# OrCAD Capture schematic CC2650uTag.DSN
size A4; title: CC2650uTag; rev: 2.0.0
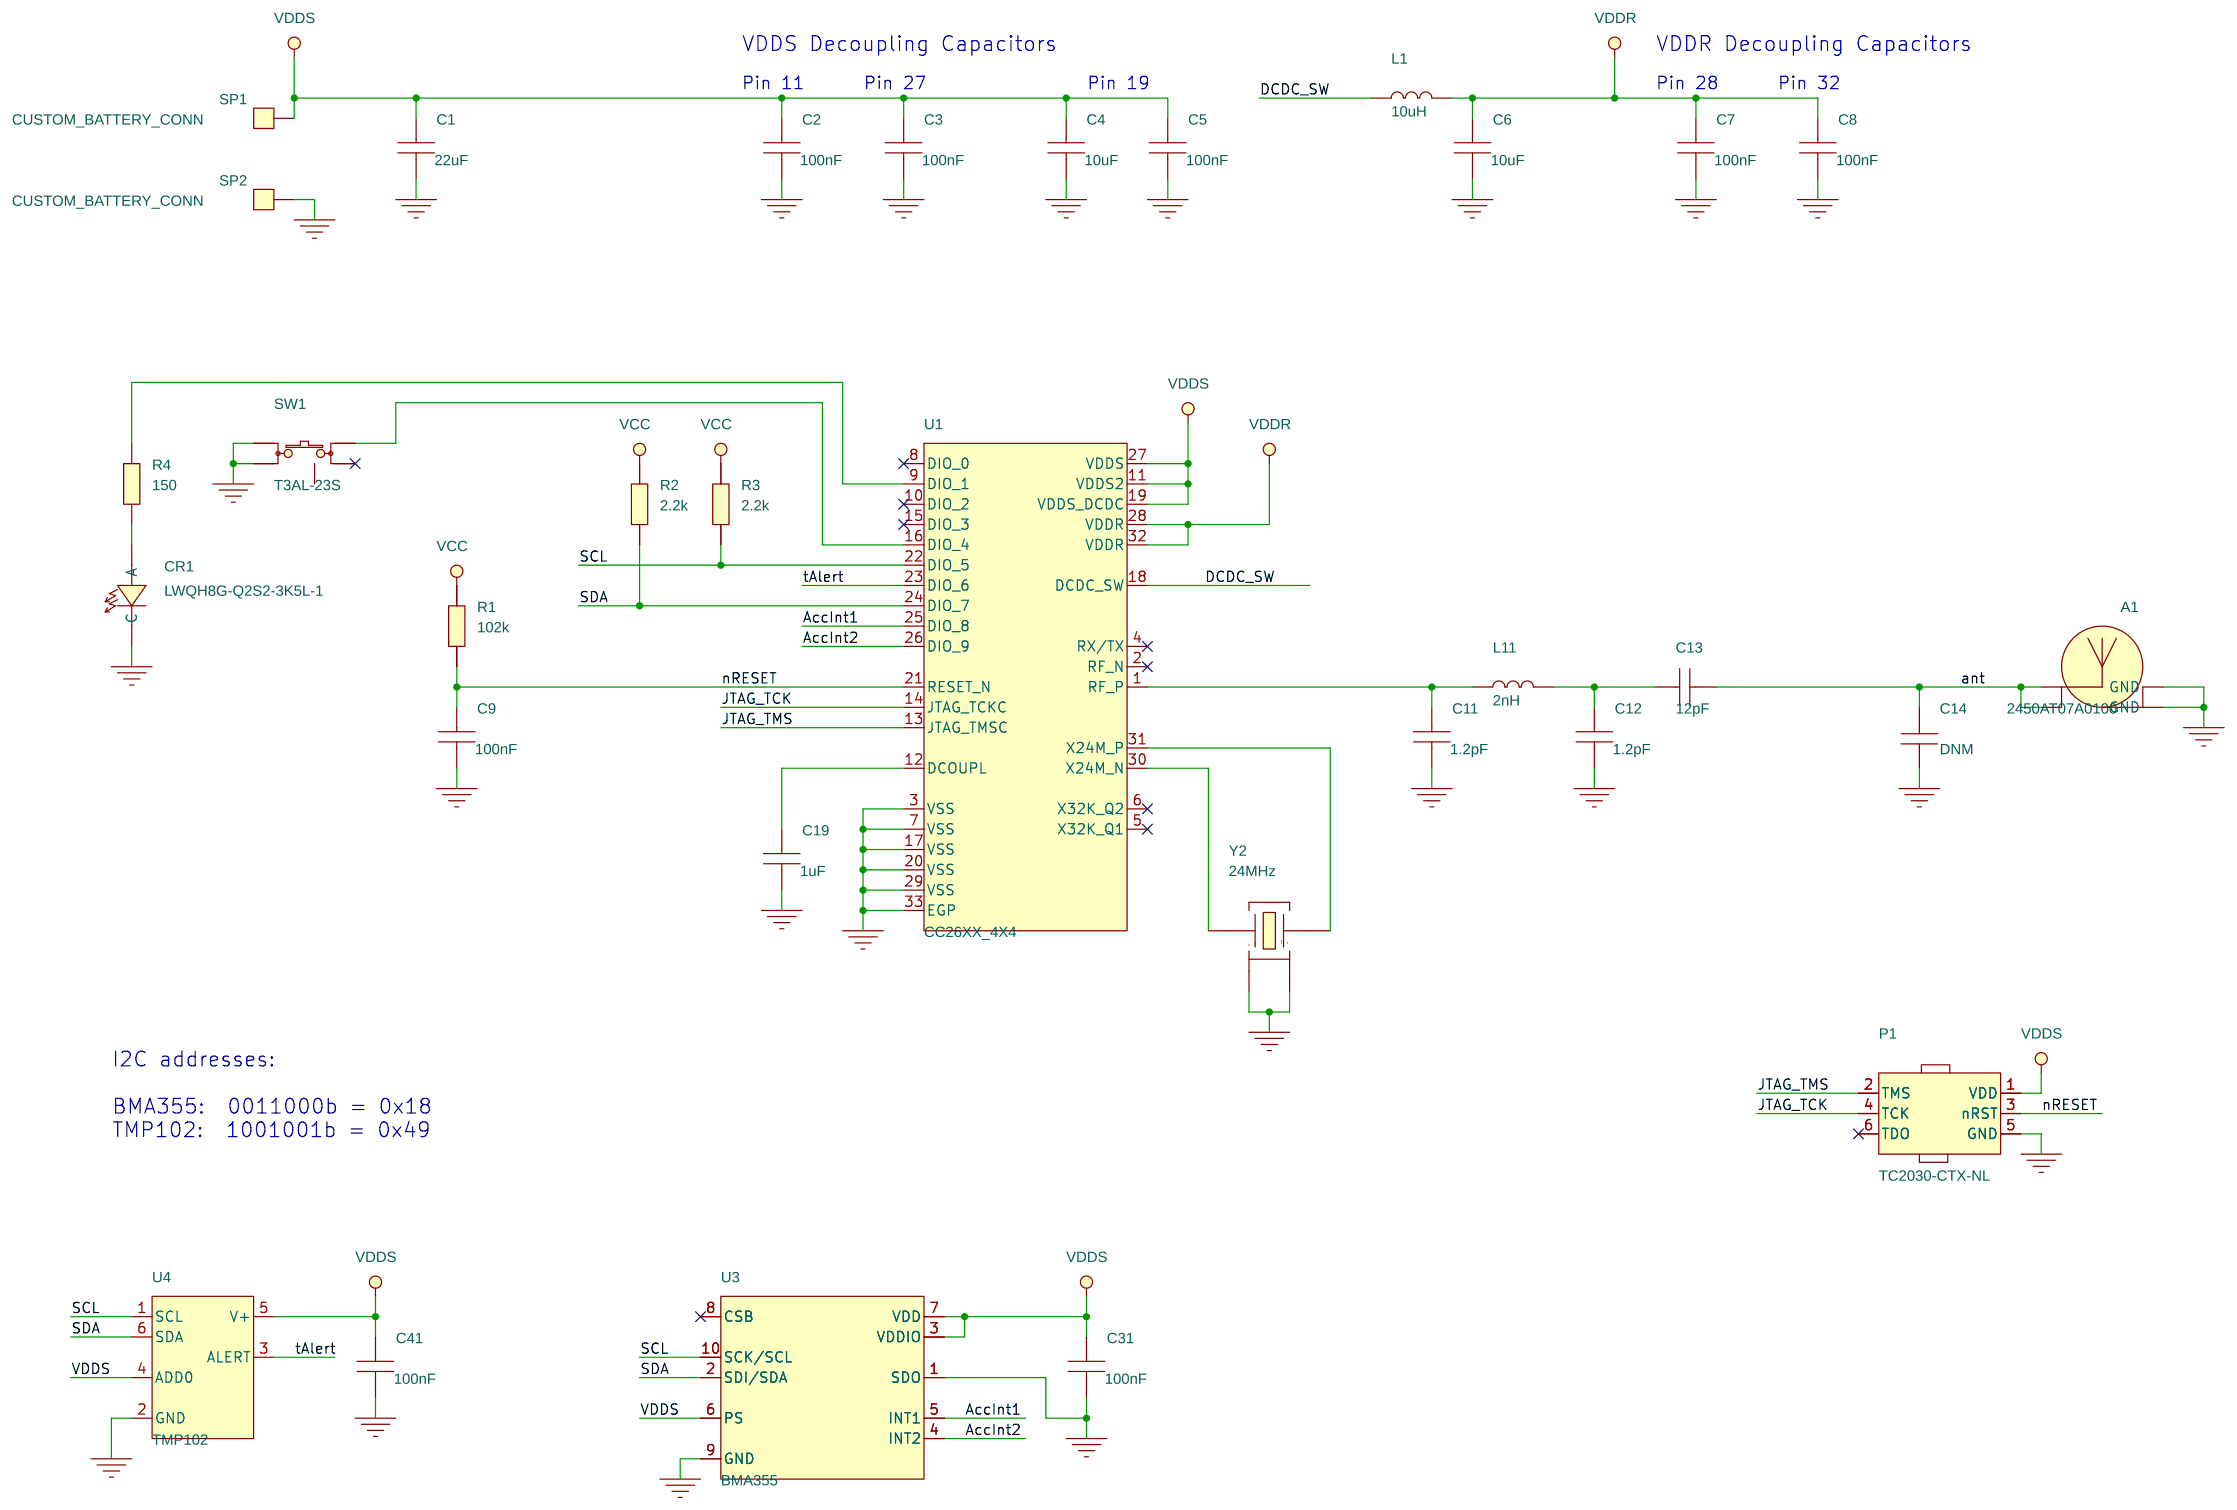
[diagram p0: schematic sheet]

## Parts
A1  2450AT07A0100  [ANTENNA_2450AT07A0100N]
C1  22uF  [CAPC1608X90L]
C2  100nF  [CAPC0603X35L]
C3  100nF  [CAPC0603X35L]
C4  10uF  [CAPC1005X60L]
C5  100nF  [CAPC0603X35L]
C6  10uF  [CAPC1005X60L]
C7  100nF  [CAPC0603X35L]
C8  100nF  [CAPC0603X35L]
C9  100nF  [CAPC0603X35L]
C11  1.2pF  [CAPC0603X35L]
C12  1.2pF  [CAPC0603X35L]
C13  12pF  [CAPC0603X35L]
C14  DNM  [CAPC0603X35L]
C19  1uF  [CAPC1005X60L]
C31  100nF  [CAPC0603X35L]
C41  100nF  [CAPC0603X35L]
CR1  LWQH8G-Q2S2-3K5L-1  [LED_LWQH8GQ2S23K5L1L]
L1  10uH  [INDC1608X100L]
L11  2nH  [INDC1005X60L]
P1  TC2030-CTX-NL  [TAGCONNECT_TC2030-CTX-NLL]
R1  102k  [RESC0603X35L]
R2  2.2k  [RESC0603X35L]
R3  2.2k  [RESC0603X35L]
R4  150  [RESC0603X35L]
SP1  CUSTOM_BATTERY_CONN  [PAD_S2800OBL5000_800M3000]
SP2  CUSTOM_BATTERY_CONN  [PAD_S2800OBL5000_800M3000]
SW1  T3AL-23S  [SW_T3AL23SQTL]
U1  CC26XX_4X4  [QFNFC40P400X400X100-33L]
U3  BMA355  [BGAFC10C40P125X152X80]
U4  TMP102  [SOTFL50P160X60-6L]
Y2  24MHz  [XTAL_FA128L]

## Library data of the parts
A1 = ANTENNA_CERAMIC_4: MECHANIC, ANTENNA, HIGH FREQUENCY CERAMIC, 50, 2.4GHz TO 2.5GHz, SMD; ALT_SYMBOLS: ANTENNA_2450AT07A0100L,ANTENNA_2450AT07A0100M; AutoDoc File: http://notefied-dynamic-precision.com/DB/Apps/Desktop/Item/Object.aspx?id=90750; Datasheet URL 2: http://www.johansontechnology.com/images/stories/ip/rf-antennas/Antenna_2450AT07A0100_v5.pdf; FPLIST: ANTENNA_2450AT07A0100N,ANTENNA_2450AT07A0100L,ANTENNA_2450AT07A0100M; Frequency: 2.4GHz TO 2.5GHz; Impedance: 50; MPN Status: ACTIVE; Manufacturer: JOHANSON DIELECTRICS; Max Oper Temp: +85DEGC; Min Oper Temp: -40DEGC; Mounting Type: SMD; NOTE Status: PREFERRED; Part Number: 13-00495; Part Type: MECHANIC\ANTENNA; Revision: R001; RoHS Status: ROHS_COMPLIANT; Rtd Power: 2W
C1 = CAPACITOR: CAPACITOR, CERAMIC X5R, 22uF, 4V, -20%/+20%, -55DEGC/+85DEGC, 0603, SMD; ALT_SYMBOLS: CAPC1608X90L,CAPC1608X90M; AutoDoc File: http://notefied-dynamic-precision.com/DB/Apps/Desktop/Item/Object.aspx?id=86641; Budget Currency: EUR; Budget Price: 0.122; Datasheet URL 1: http://search.murata.co.jp/Ceramy/image/img/w_hinm/L0005E.pdf; Datasheet URL 2: http://psearch.murata.com/capacitor/product/GRM188R60G226MEA0%23.pdf; Definied Quality: INDUSTRIAL; Dielectric Type: X5R; Esd Level: N/A; FPLIST: CAPC1608X90N,CAPC1608X90L,CAPC1608X90M; Last Time Buy: N/A; Lead Time: 20; MPN: GRM188R60G226MEA0D; MPN Status: ACTIVE; MSL: 1; MTBF: N/A; MTBF Standard: N/A; Manufacturer: MURATA; Max Oper Temp: +85DEGC; Max Tol: +20%; Min Oper Temp: -55DEGC; Min Tol: -20%; Mounting Type: SMD; NOTE Status: PREFERRED; Old Footprint: CAPC1608X90N; PCB Package: 0603; Packing Size: 4000; Packing Type: TAPE_&_REEL; Part Number: 02-04481; Part Type: CAPACITOR\CERAMIC\0603; Revision: R001; RoHS Status: ROHS_COMPLIANT; Rtd Voltage: 4V; WEIGHT: 0.0091g
C2 C3 C5 C7-C9 C31 C41 = CAPACITOR: CAPACITOR, CERAMIC X5R, 100nF, 6.3V, -10%/+10%, -55DEGC/+85DEGC, 0201, SMD; ALT_SYMBOLS: CAPC0603X35L,CAPC0603X35M; AutoDoc File: http://notefied-dynamic-precision.com/DB/Apps/Desktop/Item/Object.aspx?id=82835; Budget Currency: EUR; Budget Price: 0.073; Datasheet URL 1: N/A; Datasheet URL 2: http://www.avx.com/docs/Catalogs/cx5r.pdf; Definied Quality: INDUSTRIAL; Dielectric Type: X5R; FPLIST: CAPC0603X35N,CAPC0603X35L,CAPC0603X35M; Lead Time: 16; MPN: 02016D104KAT2A; MPN Status: ACTIVE; MSL: 1; MTBF: N/A; MTBF Standard: N/A; Manufacturer: AVX; Max Oper Temp: +85DEGC; Max Tol: +10%; Min Oper Temp: -55DEGC; Min Tol: -10%; Mounting Type: SMD; NOTE Status: PREFERRED; Old Footprint: CAPC0603X35N; PCB Package: 0201; Packing Size: 15000; Packing Type: TAPE_&_REEL; Part Number: 02-01686; Part Type: CAPACITOR\CERAMIC\0201; Revision: R002; RoHS Status: ROHS_COMPLIANT; Rtd Voltage: 6.3V; WEIGHT: N/A
C4 C6 = CAPACITOR: CAPACITOR, CERAMIC X5R, 10uF, 6.3V, -20%/+20%, -55DEGC/+85DEGC, 0402, SMD; ALT_SYMBOLS: CAPC1005X60L,CAPC1005X60M; AutoDoc File: http://notefied-dynamic-precision.com/DB/Apps/Desktop/Item/Object.aspx?id=90722; Budget Currency: EUR; Budget Price: 0.13; Datasheet URL 1: N/A; Datasheet URL 2: http://product.tdk.com/capacitor/mlcc/en/documents/C1005X5R0J106M050BC.pdf; Definied Quality: INDUSTRIAL; Dielectric Type: X5R; Esd Level: N/A; FPLIST: CAPC1005X60N,CAPC1005X60L,CAPC1005X60M; Last Time Buy: N/A; Lead Time: 18; MPN: C1005X5R0J106M050BC; MPN Status: ACTIVE; MSL: N/A; MTBF: N/A; MTBF Standard: N/A; Manufacturer: TDK; Max Oper Temp: +85DEGC; Max Tol: +20%; Min Oper Temp: -55DEGC; Min Tol: -20%; Mounting Type: SMD; NOTE Status: PREFERRED; Old Footprint: CAPC1005X60N; PCB Package: 0402; Packing Size: 10000; Packing Type: TAPE_&_REEL; Part Number: 02-05030; Part Type: CAPACITOR\CERAMIC\0402; Revision: R001; RoHS Status: ROHS_COMPLIANT; Rtd Voltage: 6.3V; WEIGHT: N/A
C11 C12 = CAPACITOR: CAPACITOR, CERAMIC C0G/NP0, 1.2pF, 25V, -0.25pF/+0.25pF, -55DEGC/+125DEGC, 0201, SMD; ALT_SYMBOLS: CAPC0603X35L,CAPC0603X35M; AutoDoc File: http://notefied-dynamic-precision.com/DB/Apps/Desktop/Item/Object.aspx?id=85776; Budget Currency: EUR; Budget Price: 0.062; Datasheet URL 1: N/A; Datasheet URL 2: http://www.avx.com/docs/Catalogs/ccog.pdf; Definied Quality: INDUSTRIAL; Dielectric Type: C0G/NP0; FPLIST: CAPC0603X35N,CAPC0603X35L,CAPC0603X35M; Lead Time: 12; LifeCycle Status: ACTIVE; MPN: 02013A1R2CAT2A; MPN Status: ACTIVE; MSL: 1; MTBF: N/A; MTBF Standard: N/A; Manufacturer: AVX; Max Oper Temp: +125DEGC; Max Tol: +0.25pF; Min Oper Temp: -55DEGC; Min Tol: -0.25pF; Mounting Type: SMD; NOTE Status: PREFERRED; Old Footprint: CAPC0603X35N; PCB Package: 0201; Packing Size: 15000; Packing Type: TAPE_&_REEL; Part Number: 02-04266; Part Type: CAPACITOR\CERAMIC\0201; Revision: R001; RoHS Status: ROHS_COMPLIANT; Rtd Voltage: 25V; WEIGHT: 0.000228g
C13 = CAPACITOR: CAPACITOR, CERAMIC C0G/NP0, 12pF, 25V, -5%/+5%, -55DEGC/+125DEGC, 0201, SMD; ALT_SYMBOLS: CAPC0603X35L,CAPC0603X35M; AutoDoc File: http://notefied-dynamic-precision.com/DB/Apps/Desktop/Item/Object.aspx?id=85787; Budget Currency: EUR; Budget Price: 0.043; Datasheet URL 1: N/A; Datasheet URL 2: http://www.avx.com/docs/Catalogs/ccog.pdf; Definied Quality: INDUSTRIAL; Dielectric Type: C0G/NP0; FPLIST: CAPC0603X35N,CAPC0603X35L,CAPC0603X35M; Lead Time: 18; LifeCycle Status: ACTIVE; MPN: 02013A120JAT2A; MPN Status: ACTIVE; MSL: 1; MTBF: N/A; MTBF Standard: N/A; Manufacturer: AVX; Max Oper Temp: +125DEGC; Max Tol: +5%; Min Oper Temp: -55DEGC; Min Tol: -5%; Mounting Type: SMD; NOTE Status: PREFERRED; Old Footprint: CAPC0603X35N; PCB Package: 0201; Packing Size: 15000; Packing Type: TAPE_&_REEL; Part Number: 02-04277; Part Type: CAPACITOR\CERAMIC\0201; Revision: R001; RoHS Status: ROHS_COMPLIANT; Rtd Voltage: 25V; WEIGHT: N/A
C14 = CAPACITOR: CAPACITOR, DO NOT MOUNT, 0201, SMD; ALT_SYMBOLS: CAPC0603X35L,CAPC0603X35N; AutoDoc File: https://notefied-dynamic-precision.com/NotefiedWebServices/AutoDocs.aspx?itemid=50471; FPLIST: CAPC0603X35N,CAPC0603X35L,CAPC0603X35N; Old Footprint: CAPC0603X35N,0201; Part Number: 02-01320; Part Type: CAPACITOR\CERAMIC\0201; Revision: R001
C19 = CAPACITOR: CAPACITOR, CERAMIC X5R, 1uF, 10V, -10%/+10%, -55DEGC/+85DEGC, 0402, SMD; ALT_SYMBOLS: CAPC1005X60L,CAPC1005X60M; AutoDoc File: http://notefied-dynamic-precision.com/DB/Apps/Desktop/Item/Object.aspx?id=74236; Budget Currency: EUR; Budget Price: 0.015; Datasheet URL 1: http://search.murata.co.jp/Ceramy/image/img/w_hinm/L0005E.pdf; Datasheet URL 2: http://psearch.murata.com/capacitor/product/GRM155R61A105KE15%23.pdf; Definied Quality: INDUSTRIAL; Dielectric Type: X5R; Esd Level: N/A; FPLIST: CAPC1005X60N,CAPC1005X60L,CAPC1005X60M; Last Time Buy: N/A; Lead Time: 14; MPN: GRM155R61A105KE15D; MPN Status: ACTIVE; MSL: 1; MTBF: N/A; MTBF Standard: N/A; Manufacturer: MURATA; Max Oper Temp: +85DEGC; Max Tol: +10%; Min Oper Temp: -55DEGC; Min Tol: -10%; Mounting Type: SMD; NOTE Status: PREFERRED; Old Footprint: CAPC1005X60N,0402; PCB Package: 0402; Packing Size: 10000; Packing Type: TAPE_&_REEL; Part Number: 02-02381; Part Type: CAPACITOR\CERAMIC\0402; Revision: R002; RoHS Status: ROHS_COMPLIANT; Rtd Voltage: 10V; WEIGHT: 0.0016g
CR1 = LED: OPTO, LED, InGaN, WHITE, 2.6V TO 3.1V, 0.015A, 0402, SMD; ALT_SYMBOLS: LED_LWQH8GQ2S23K5L1L,LED_LWQH8GQ2S23K5L1M; AutoDoc File: http://notefied-dynamic-precision.com/DB/Apps/Desktop/Item/Object.aspx?id=95594; Datasheet URL 2: http://catalog.osram-os.com/catalogue/catalogue.do;jsessionid=5C056371528898F0F981A18D4C0143E0?act=downloadFile&favOid=0200000200033af5000300b6; FPLIST: LED_LWQH8GQ2S23K5L1N,LED_LWQH8GQ2S23K5L1L,LED_LWQH8GQ2S23K5L1M; MPN: LW QH8G-Q2S2-3K5L-1; MPN Status: ACTIVE; Manufacturer: OSRAM; Max Oper Temp: +85DEGC; Min Oper Temp: -40DEGC; Mounting Type: SMD; NOTE Status: PREFERRED; Old Footprint: LED_LWQH8GQ2S23K5L1N; PCB Package: 0402; Packing Size: 4000; Packing Type: TAPE_&_REEL; Part Number: 15-01260; Part Type: OPTO\LED\0402; Revision: R001; RoHS Status: ROHS_COMPLIANT; Rtd Current: 0.015A; Rtd Voltage: 2.6V TO 3.1V
L1 = INDUCTOR: INDUCTOR, CHIP, 10uH, -20%/+20%, 0.25A, -55DEGC/+125DEGC, 0603, SMD; ALT_SYMBOLS: INDC1608X100L,INDC1608X100M; AutoDoc File: http://notefied-dynamic-precision.com/DB/Apps/Desktop/Item/Object.aspx?id=84900; Budget Currency: EUR; Budget Price: 0.038; Datasheet URL 1: N/A; Datasheet URL 2: http://www.tdk.co.jp/tefe02/e533_mlz.pdf; Definied Quality: INDUSTRIAL; FPLIST: INDC1608X100N,INDC1608X100L,INDC1608X100M; Lead Time: 4; MPN: MLZ1608M100WT000; MPN Status: ACTIVE; MSL: N/A; MTBF: N/A; MTBF Standard: N/A; Manufacturer: TDK; Max Oper Temp: +125DEGC; Max Tol: +20%; Min Oper Temp: -55DEGC; Min Tol: -20%; Mounting Type: SMD; NOTE Status: PREFERRED; Old Footprint: INDC1608X100N; PCB Package: 0603; Packing Size: 4000; Packing Type: TAPE_&_REEL; Part Number: 03-06510; Part Type: INDUCTOR\CHIP\0603; Revision: R001; RoHS Status: ROHS_COMPLIANT; Rtd Current: 0.25A; WEIGHT: 0.004g
L11 = INDUCTOR: INDUCTOR, CHIP, 2nH, -0.3nH/ +0.3nH, 0.3A, -55DEGC/+125DEGC, 0402, SMD; ALT_SYMBOLS: INDC1005X60L,INDC1005X60M; AutoDoc File: http://notefied-dynamic-precision.com/DB/Apps/Desktop/Item/Object.aspx?id=85431; Budget Currency: EUR; Budget Price: 0.021; Datasheet URL 1: http://search.murata.co.jp/Ceramy/image/img/PDF/ENG/L0075S0083LQG15HS.pdf; Datasheet URL 2: http://search.murata.co.jp/Ceramy/image/img/PDF/ENG/L0075S0083LQG15HS.pdf; FPLIST: INDC1005X60N,INDC1005X60L,INDC1005X60M; Frequency: 6GHz; Lead Time: 9; MPN: LQG15HS2N0S02D; MPN Status: ACTIVE; Manufacturer: MURATA; Max Oper Temp: +125DEGC; Max Tol: +0.3nH; Min Oper Temp: -55DEGC; Min Tol: -0.3nH; Mounting Type: SMD; NOTE Status: PREFERRED; Old Footprint: INDC1005X60N; PCB Package: 0402; Packing Size: 10000; Packing Type: TAPE_&_REEL; Part Number: 03-06525; Part Type: INDUCTOR\CHIP\0402; Revision: R001; RoHS Status: ROHS_COMPLIANT; Rtd Current: 0.3A; WEIGHT: 0.001g
P1 = CONN_IDC_TC2030-CTX-NL_0: NON COMPONENT, CONNECTOR CABLE, PLUG OF NAILS, 6 PINS, 2 ROWS, SMD; ALT_SYMBOLS: TAGCONNECT_TC2030-CTX-NLL,TAGCONNECT_TC2030-CTX-NLM; AutoDoc File: http://notefied-dynamic-precision.com/DB/Apps/Desktop/Item/Object.aspx?id=96375; FPLIST: TAGCONNECT_TC2030-CTX-NLN,TAGCONNECT_TC2030-CTX-NLL,TAGCONNECT_TC2030-CTX-NLM; Old Footprint: TAGCONNECT_TC2030-CTX-NLN; Part Number: 19-00447; Part Type: NON_COMPONENT\CONNECTOR; Revision: R001
R1 = RESISTOR: RESISTOR, THICK FILM, 102K, -1%/+1%, 0.05W, 30V, -55DEGC/+125DEGC, 0201, SMD; ALT_SYMBOLS: RESC0603X35L,RESC0603X35M; AutoDoc File: http://notefied-dynamic-precision.com/DB/Apps/Desktop/Item/Object.aspx?id=58760; Budget Currency: EUR; Budget Price: 0.045; Datasheet URL 1: http://www.vishay.com/docs/20035/dcrcwe3.pdf; Datasheet URL 2: http://www.vishay.com/docs/20052/crcw0201e3.pdf; Definied Quality: COMMERCIAL; FPLIST: RESC0603X35N,RESC0603X35L,RESC0603X35M; Lead Time: 8; LifeCycle Status: ACTIVE; MPN: CRCW0201102KFKED; MPN Status: ACTIVE; MSL: 1; MTBF: 1.00*10^10; MTBF Standard: CL=90%; Manufacturer: VISHAY; Max Oper Temp: +125DEGC; Max TC: +100PPM/DEGC; Max Tol: +1%; Min Oper Temp: -55DEGC; Min TC: -100PPM/DEGC; Min Tol: -1%; Mounting Type: SMD; NOTE Status: PREFERRED; Old Footprint: RESC0603X35N,0201; PCB Package: 0201; Packing Size: 10000; Packing Type: TAPE_&_REEL; Part Number: 01-03953; Part Type: RESISTOR\0201\PRECISION; Resistor Type: THICK FILM; Revision: R001; RoHS Status: ROHS_COMPLIANT; Rtd Power: 0.05W; Rtd Voltage: 30V; WEIGHT: 0.00017g
R2 R3 = RESISTOR: RESISTOR, THICK FILM, 2K2, -1%/+1%, 0.05W, 30V, -55DEGC/+125DEGC, 0201, SMD; ALT_SYMBOLS: RESC0603X35L,RESC0603X35M; AutoDoc File: http://notefied-dynamic-precision.com/DB/Apps/Desktop/Item/Object.aspx?id=58879; Budget Currency: EUR; Budget Price: 0.045; Datasheet URL 1: http://www.vishay.com/docs/20035/dcrcwe3.pdf; Datasheet URL 2: http://www.vishay.com/docs/20052/crcw0201e3.pdf; Definied Quality: COMMERCIAL; FPLIST: RESC0603X35N,RESC0603X35L,RESC0603X35M; Lead Time: 9; LifeCycle Status: ACTIVE; MPN: CRCW02012K20FKED; MPN Status: ACTIVE; MSL: 1; MTBF: 1.00*10^10; MTBF Standard: CL=90%; Manufacturer: VISHAY; Max Oper Temp: +155DEGC; Max TC: +100PPM/DEGC; Max Tol: +1%; Min Oper Temp: -55DEGC; Min TC: -100PPM/DEGC; Min Tol: -1%; Mounting Type: SMD; NOTE Status: PREFERRED; Old Footprint: RESC0603X35N,0201; PCB Package: 0201; Packing Size: 10000; Packing Type: TAPE_&_REEL; Part Number: 01-04072; Part Type: RESISTOR\0201\PRECISION; Resistor Type: THICK FILM; Revision: R001; RoHS Status: ROHS_COMPLIANT; Rtd Power: 0.05W; Rtd Voltage: 30V; WEIGHT: 0.00017g
R4 = RESISTOR: RESISTOR, THICK FILM, 150, -1%/+1%, 0.05W, 30V, -55DEGC/+155DEGC, 0201, SMD; ALT_SYMBOLS: RESC0603X35L,RESC0603X35M; AutoDoc File: http://notefied-dynamic-precision.com/DB/Apps/Desktop/Item/Object.aspx?id=58187; Budget Currency: EUR; Budget Price: 0.045; Datasheet URL 1: http://www.vishay.com/docs/20035/dcrcwe3.pdf; Datasheet URL 2: http://www.vishay.com/docs/20052/crcw0201e3.pdf; Definied Quality: COMMERCIAL; FPLIST: RESC0603X35N,RESC0603X35L,RESC0603X35M; Lead Time: 9; LifeCycle Status: ACTIVE; MPN: CRCW0201150RFKED; MPN Status: ACTIVE; MSL: 1; MTBF: 1.00*10^10; MTBF Standard: CL=90%; Manufacturer: VISHAY; Max Oper Temp: +155DEGC; Max TC: +100PPM/DEGC; Max Tol: +1%; Min Oper Temp: -55DEGC; Min TC: -100PPM/DEGC; Min Tol: -1%; Mounting Type: SMD; NOTE Status: PREFERRED; Old Footprint: RESC0603X35N,0201; PCB Package: 0201; Packing Size: 10000; Packing Type: TAPE_&_REEL; Part Number: 01-03380; Part Type: RESISTOR\0201\PRECISION; Resistor Type: THICK FILM; Revision: R001; RoHS Status: ROHS_COMPLIANT; Rtd Power: 0.05W; Rtd Voltage: 30V; WEIGHT: 0.00017g
SP1 SP2 = SINGLEPAD: NON COMPONENT, PAD FOR CUSTOM BATTERY CONNECTOR, 2.8x5mm WITH A DRILLED SLOT 0.8x3mm, PTH; AutoDoc File: https://notefied-dynamic-precision.com/NotefiedWebServices/AutoDocs.aspx?itemid=87781; FPLIST: PAD_S2800OBL5000_800M3000,; Part Number: 19-00353; Part Type: NON_COMPONENT\PAD; Revision: R001
SW1 = SWITCH_TACT_V1: SWITCH, TACT, 0.05A@12V, 0.05A, 12V, SMD; ALT_SYMBOLS: SW_T3AL23SQTL,SW_T3AL23SQTM; AutoDoc File: http://notefied-dynamic-precision.com/DB/Apps/Desktop/Item/Object.aspx?id=95026; Datasheet URL 1: http://www.diptronics.nl/Pages/pag2B_INDEX.html; Datasheet URL 2: http://www.dip.com.tw/en/en-product-information/en-switch004/item/download/280_3852849316f0ada691bef78deea85ea4; FPLIST: SW_T3AL23SQTN,SW_T3AL23SQTL,SW_T3AL23SQTM; MPN: T3AL-23S-Q-T; MPN Status: ACTIVE; Manufacturer: DIPTRONICS; Max Oper Temp: +85DEGC; Min Oper Temp: -40DEGC; Mounting Type: SMD; NOTE Status: PREFERRED; Old Footprint: SW_T3AL23SQTN; Packing Size: 8000; Packing Type: TAPE_&_REEL; Part Number: 08-00158; Part Type: SWITCH\TACT; Revision: R001; RoHS Status: ROHS_COMPLIANT; Rtd Current: 0.05A; Rtd Voltage: 12V
U1 = IC_RF_CC26XX_QFN32_2: IC, ANALOG, CUSTOM, CC26XX 4x4 DCDC, QFN32, SMD; ALT_SYMBOLS: QFNFC40P400X400X100-33L,QFNFC40P400X400X100-33M; AutoDoc File: http://notefied-dynamic-precision.com/DB/Apps/Desktop/Item/Object.aspx?id=88777; FPLIST: QFNFC40P400X400X100-33N,QFNFC40P400X400X100-33L,QFNFC40P400X400X100-33M; MPN Status: ACTIVE; Manufacturer: TEXAS INSTRUMENTS; Max Oper Temp: N/A; Min Oper Temp: N/A; Mounting Type: SMD; NOTE Status: PREFERRED; Old Footprint: QFNFC40P400X400X100-33N; PCB Package: QFN32; Part Number: 18-28498; Part Type: IC\ANALOG\OTHER; Revision: R001; RoHS Status: PART NOT KNOWN; Rtd Voltage: N/A
U3 = IC_ACC_BMA355_WLCSP10: IC, TRANSDUCER, ACCELERATION, 1.62V TO 3.6V, WLCSP10, SMD; AutoDoc File: http://notefied-dynamic-precision.com/DB/Apps/Desktop/Item/Object.aspx?id=95795; Datasheet URL 1: N/A; Datasheet URL 2: https://www.bosch-sensortec.com/en/homepage/products_3/3_axis_sensors/acceleration_sensors/bma355_2/bma355_3; FPLIST: BGAFC10C40P125X152X80,; MPN Status: PRELIMINARY; Manufacturer: BOSCH; Max Oper Temp: +85DEGC; Min Oper Temp: -40DEGC; Mounting Type: SMD; NOTE Status: PREFERRED; PCB Package: WLCSP10; Part Number: 18-29306; Part Type: IC\TRANSDUCER\ACCELERATION; Revision: R001; RoHS Status: PART NOT KNOWN; Rtd Voltage: 1.62V TO 3.6V
U4 = TMP302_2: IC, TRANSDUCER, TEMPERATURE SWITCH, 1.4V TO 3.6V, SOT-563, SMD; ALT_SYMBOLS: SOTFL50P160X60-6L,SOTFL50P160X60-6M; AutoDoc File: http://notefied-dynamic-precision.com/DB/Apps/Desktop/Item/Object.aspx?id=86018; Budget Currency: USD; Budget Price: 0.23; Datasheet URL 1: N/A; Datasheet URL 2: http://www.ti.com/lit/ds/symlink/tmp302b.pdf; Definied Quality: INDUSTRIAL; Esd Level: HBM 2kV; FPLIST: SOTFL50P160X60-6N,SOTFL50P160X60-6L,SOTFL50P160X60-6M; Last Time Buy: N/A; Lead Time: 8; MPN: TMP302BDRLT; MPN Status: ACTIVE; MSL: 1; MTBF: 1.36*10^9; MTBF Standard: CL=60%,Td=55degC,Ea=0.7eV,Ts=125degC; Manufacturer: TEXAS INSTRUMENTS; Max Oper Temp: +125DEGC; Min Oper Temp: -40DEGC; Mounting Type: SMD; NOTE Status: PREFERRED; Old Footprint: SOTFL50P160X60-6N; PCB Package: SOT-563; Packing Size: 250; Packing Type: TAPE_&_REEL; Part Number: 18-27925; Part Type: IC\TRANSDUCER\TEMPERATURE; Revision: R001; RoHS Status: ROHS_COMPLIANT; Rtd Voltage: 1.4V TO 3.6V; WEIGHT: 0.0032g
Y2 = XTAL_4: CRYSTAL, OSCILATOR, 32MHz, 10pF, -10PPM/+10PPM, -40DEGC/+85DEGC, SMD; ALT_SYMBOLS: XTAL_FA128L,XTAL_FA128M; AutoDoc File: http://notefied-dynamic-precision.com/DB/Apps/Desktop/Item/Object.aspx?id=85460; Budget Currency: EUR; Budget Price: 0.545; Capacitance: 10pF; Datasheet URL 1: http://www.eea.epson.com/portal/pls/portal/docs/1/1529523.PDF; Datasheet URL 2: http://www.eea.epson.com/portal/pls/portal/docs/1/1529449.PDF; Definied Quality: INDUSTRIAL; Esd Level: N/A; FPLIST: XTAL_FA128N,XTAL_FA128L,XTAL_FA128M; Frequency: 32MHz; Last Time Buy: N/A; Lead Time: 13; MPN: FA-128 32MHz 10pF 10PPM; MPN Status: ACTIVE; MSL: N/A; MTBF: N/A; MTBF Standard: N/A; Manufacturer: EPSON; Max Oper Temp: +85DEGC; Max Tol: +10PPM; Min Oper Temp: -40DEGC; Min Tol: -10PPM; Mounting Type: SMD; NOTE Status: PREFERRED; Old Footprint: XTAL_FA128N; PCB Package: SMD; Packing Size: 250; Packing Type: TAPE_&_REEL; Part Number: 12-00422; Part Type: CRYSTAL\OSCILLATOR\MEMS; Revision: R001; RoHS Status: ROHS_COMPLIANT; WEIGHT: N/A

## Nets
GND: A1.2(GND) A1.3(GND) C1.2 C2.2 C3.2 C4.2 C5.2 C6.2 C7.2 C8.2 C9.2 C11.2 C12.2 C14.1 C19.2 C31.2 C41.2 CR1.1(C) P1.5(GND) SP2.1 SW1.1 SW1.2 U1.3(VSS) U1.7(VSS) U1.17(VSS) U1.20(VSS) U1.29(VSS) U1.33(EGP) U3.1(SDO) U3.9(GND) U4.2(GND) Y2.2 Y2.4
VDDR: C6.1 C7.1 C8.1 L1.2 U1.28(VDDR) U1.32(VDDR)
VDDS: C1.1 C2.1 C3.1 C4.1 C5.1 C31.1 C41.1 P1.1(VDD) R1.2 R2.2 R3.2 SP1.1 U1.11(VDDS2) U1.19(VDDS_DCDC) U1.27(VDDS) U3.3(VDDIO) U3.6(PS) U3.7(VDD) U4.4(ADD0) U4.5(V+)
AccInt1: U1.25(DIO_8) U3.5(INT1)
AccInt2: U1.26(DIO_9) U3.4(INT2)
ant: A1.1 A1.4 C13.2 C14.2
DCDC_SW: L1.1 U1.18(DCDC_SW)
JTAG_TCK: P1.4(TCK) U1.14(JTAG_TCKC)
JTAG_TMS: P1.2(TMS) U1.13(JTAG_TMSC)
nRESET: C9.1 P1.3(nRST) R1.1 U1.21(RESET_N)
SCL: R3.1 U1.22(DIO_5) U3.10(SCK/SCL) U4.1(SCL)
SDA: R2.1 U1.24(DIO_7) U3.2(SDI/SDA) U4.6(SDA)
tAlert: U1.23(DIO_6) U4.3(ALERT)
N309359: C19.1 U1.12(DCOUPL)
N323476: C11.1 L11.1 U1.1(RF_P)
N323522: C12.1 C13.1 L11.2
N626514: U1.30(X24M_N) Y2.1
N626528: U1.31(X24M_P) Y2.3
N642320: CR1.2(A) R4.1
N642580: R4.2 U1.9(DIO_1)
N644182: SW1.3 U1.16(DIO_4)

Not connected (* = marked no-connect by the designer): P1 6(TDO)*; SW1 4*; U1 2(RF_N)* 4(RX/TX)* 5(X32K_Q1)* 6(X32K_Q2)* 8(DIO_0)* 10(DIO_2)* 15(DIO_3)*; U3 8(CSB)*

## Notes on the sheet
- VDDS Decoupling Capacitors
- VDDR Decoupling Capacitors
- Pin 11
- Pin 27
- Pin 19
- Pin 28
- Pin 32
- I2C addresses:
  BMA355:  0011000b = 0x18
  TMP102:  1001001b = 0x49
